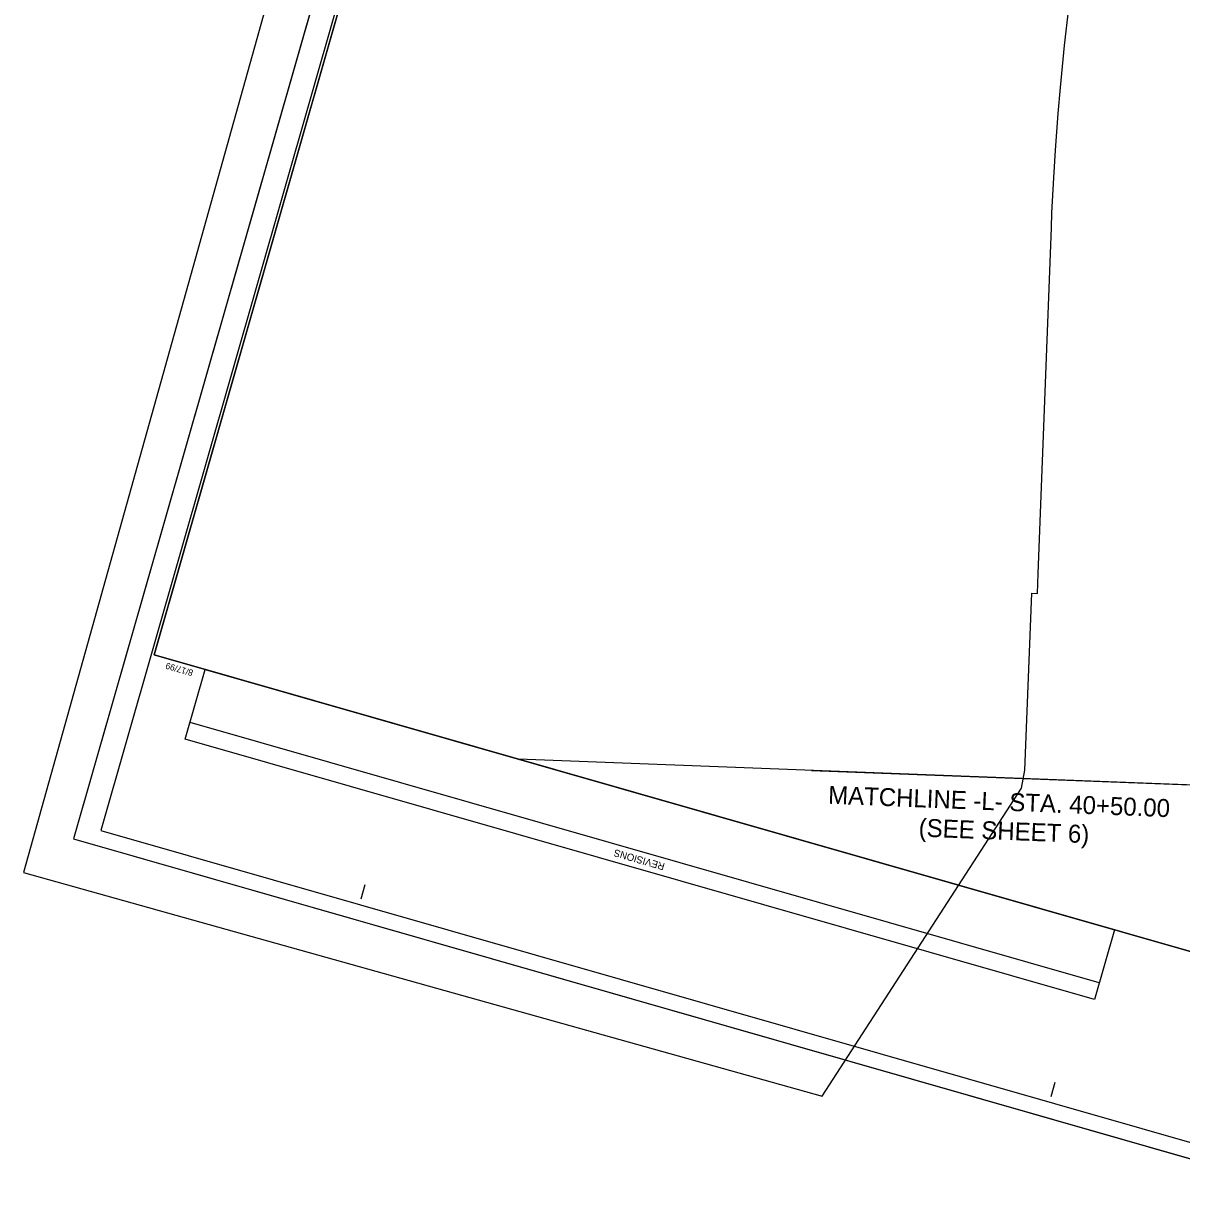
# Model space of a CAD drawing. Extents: x 2096934 to 2098492, y 687716 to 689682.
# Drawn here: x 2096934 to 2097902, y 687716 to 688699 of the extents above; entities that cross this region are included whole.
import ezdxf

# ---------------------------------------------------------------- set-up
doc = ezdxf.new("R2010")
doc.units = 0
for name, color, linetype in [('Prop Drainage Structure Bridge', 7, 'Continuous'), ('Prop Drainage Structure Catch Basin Grate 840 03F CELL', 7, 'Continuous'), ('Prop Drainage Structure Drop Inlet Grate 2 Narrow Slots and Flat Grates 840 29 CELL', 7, 'Continuous'), ('Prop Drainage Structure Drop Inlet Grate 840 16 CELL', 7, 'Continuous'), ('Prop Drainage Structure Manhole Adjust CELL', 7, 'Continuous'), ('Prop Drainage Structure Outlet Generic CELL', 7, 'Continuous'), ('Prop Drainage Structure Plot Symbol 20 Scale', 7, 'Continuous'), ('Scratch_Level_3', 7, 'Continuous'), ('Sheet Clip Boundary CELL', 7, 'Continuous')]:
    doc.layers.add(name, color=color, linetype=linetype)

msp = doc.modelspace()

# ---------------------------------------------------------------- linework, layer by layer
at = {"layer": 'Prop Drainage Structure Bridge'}
msp.add_line((2097833.26, 687897.19), (2097073.15, 688114.76), dxfattribs=at)
msp.add_lwpolyline([(2097829.28, 687883.2), (2097069.16, 688100.79), (2097085.8, 688158.99), (2097845.92, 687941.4)], close=True, dxfattribs=at)
at = {"layer": 'Prop Drainage Structure Catch Basin Grate 840 03F CELL'}
for p, q in [((2097439.02, 689635.81), (2096975.72, 688017.32)), ((2096975.72, 688017.32), (2098028.44, 687715.97))]:
    msp.add_line(p, q, dxfattribs=at)
at = {"layer": 'Prop Drainage Structure Drop Inlet Grate 2 Narrow Slots and Flat Grates 840 29 CELL'}
msp.add_line((2097592.68, 688074.63), (2097942.42, 688061.22), dxfattribs=at)
at = {"layer": 'Prop Drainage Structure Manhole Adjust CELL'}
msp.add_lwpolyline([(2097407.63, 689681.83), (2096933.93, 687989.14), (2097601.71, 687802.26), (2097768.18, 688059.85), (2097771.1, 688074.8), (2097776.76, 688222.69), (2097781.51, 688222.5), (2097782.16, 688239.21), (2097793.24, 688528.08), (2097793.53, 688540.67), (2097795.21, 688569.89), (2097796.55, 688593.09), (2097798.78, 688623.7), (2097800.73, 688645.53), (2097804.08, 688680.39), (2097807.71, 688711.73)], dxfattribs=at)
at = {"layer": 'Prop Drainage Structure Outlet Generic CELL'}
msp.add_lwpolyline([(2098028.44, 687715.97), (2098491.74, 689334.46), (2097439.02, 689635.81), (2096975.72, 688017.32)], close=True, dxfattribs=at)
at = {"layer": 'Prop Drainage Structure Plot Symbol 20 Scale'}
msp.add_lwpolyline([(2098012.79, 687733.97), (2098471.26, 689335.63), (2097457.01, 689625.98), (2096998.53, 688024.31)], close=True, dxfattribs=at)
at = {"layer": 'Scratch_Level_3'}
for p, q in [((2097043.16, 688171.19), (2097043.16, 688171.19)), ((2097216.22, 687967.18), (2097219.64, 687979.22)), ((2097793.05, 687802.09), (2097796.5, 687814.1))]:
    msp.add_line(p, q, dxfattribs=at)
for points in [[(2097455.97, 689613.3), (2097043.16, 688171.19), (2098052.61, 687882.22), (2098465.42, 689324.31)], [(2098052.61, 687882.22), (2097043.17, 688171.15), (2097400.9, 689420.95), (2097545.17, 689379.67), (2097600.23, 689571.98), (2098465.42, 689324.31)]]:
    msp.add_lwpolyline(points, close=True, dxfattribs=at)
at = {"layer": 'Sheet Clip Boundary CELL'}
for points in [[(2098102.1, 688055.1), (2097347.73, 688084.03), (2097043.16, 688171.19), (2097346.07, 689229.4), (2097355.46, 689262.19), (2097400.9, 689420.95), (2097628.1, 689355.93), (2097683.15, 689548.26), (2098465.42, 689324.31)], [(2098102.1, 688055.1), (2097347.73, 688084.03), (2097043.16, 688171.19), (2097345.95, 689228.93), (2097355.46, 689262.19), (2097400.91, 689420.95), (2097628.1, 689355.93), (2097683.15, 689548.26), (2098465.42, 689324.31)]]:
    msp.add_lwpolyline(points, close=True, dxfattribs=at)

# ---------------------------------------------------------------- texts
at = {"layer": 'Prop Drainage Structure Bridge'}
msp.add_text('REVISIONS', height=6, rotation=164.02589, dxfattribs=at).set_placement((2097470.52, 687996.81))
at = {"layer": 'Prop Drainage Structure Drop Inlet Grate 840 16 CELL'}
for s, p in [('MATCHLINE -L- STA. 40+50.00', (2097606.4, 688046.77)), ('(SEE SHEET 6)', (2097682.08, 688019.39))]:
    msp.add_text(s, height=15, rotation=357.73729, dxfattribs=at).set_placement(p)
at = {"layer": 'Scratch_Level_3'}
msp.add_text('8/17/99', height=5.25, rotation=164.02589, dxfattribs=at).set_placement((2097076.14, 688158.39))

doc.saveas('drawing.dxf')
